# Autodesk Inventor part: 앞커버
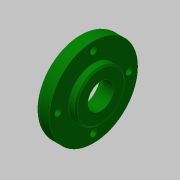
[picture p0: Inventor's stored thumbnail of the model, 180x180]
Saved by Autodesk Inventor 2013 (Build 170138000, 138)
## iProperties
Created: 2015-12
Part Number: 앞커버
Document SubType Name: Modeling
Designer: mdu
Density: 2.71 g/cm^3
Material: 알루미늄 6061
Author: mdu
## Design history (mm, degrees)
sketch "스케치1"
  geometry: L1 (-7.5, 0)-(7.5, 0); L2 (-7.5, 0)-(-7.5, 31); L3 (-7.5, 31)-(2.5, 31); L4 (2.5, 31)-(2.5, 17.5); L5 (2.5, 17.5)-(7.5, 17.5); L6 (7.5, 17.5)-(7.5, 0); 2 further points
  constraints: 12 end point, 3 perpendicular, 1 coincident, 1 horizontal, 1 midpoint, 1 parallel
  dimensions: "d0" = 15 distance of L1.start L1.end; "d1" = 62 diameter of L3 L1; "d2" = 35 diameter of L5 L1; "d5" = 10 distance of L2.end L3.end
revolve "회전1" sketch "스케치1" stored, may be unused: angle "d6" = 90 deg
sketch "스케치2" dims "d42" = 50
  geometry: 3 further points
  constraints: 2 vertical alignment, 1 coincident, 2 other
hole "구멍1" sketch "스케치2" at (0, 25) diameter "d8" = 4.5; stored, may be unused: countersink angle "d12" = 90 deg, drill point angle "d14" = 118 deg; dims "d9" = 6, "d10" = 8, "d11" = 4.4, "d13" = 8
hole "구멍2" diameter "d20" = 18; stored, may be unused: countersink angle "d24" = 90 deg, drill point angle "d26" = 0 deg; dims "d18" = 10, "d19" = 10, "d21" = 6, "d22" = 8, "d23" = 4.4, "d25" = 8
hole "구멍3" diameter "d34" = 30; stored, may be unused: countersink angle "d38" = 90 deg, drill point angle "d40" = 0 deg; dims "d32" = 10, "d33" = 10, "d35" = 6, "d36" = 4, "d37" = 2, "d39" = 7.3
fillet "모깎기1" dims "d27" = 3, "d41" = 0.3
chamfer "모따기1" distance "d29" = 0.7; stored, may be unused: second distance "d30" = 2, angle "d31" = 30 deg
chamfer "모따기2" distance "d44" = 1; stored, may be unused: second distance "d45" = 2, angle "d46" = 45 deg
node "솔리드1"
pattern_circular "원형 패턴1" dims angle "d16" = 360 deg
